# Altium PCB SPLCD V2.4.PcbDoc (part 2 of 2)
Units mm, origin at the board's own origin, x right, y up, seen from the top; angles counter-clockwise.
Board outline 130.07 x 120.05 mm, 4 copper layers (TopLayer, GND, PWR, BottomLayer); 151 components, 101 nets, 494 pads, 228 vias.
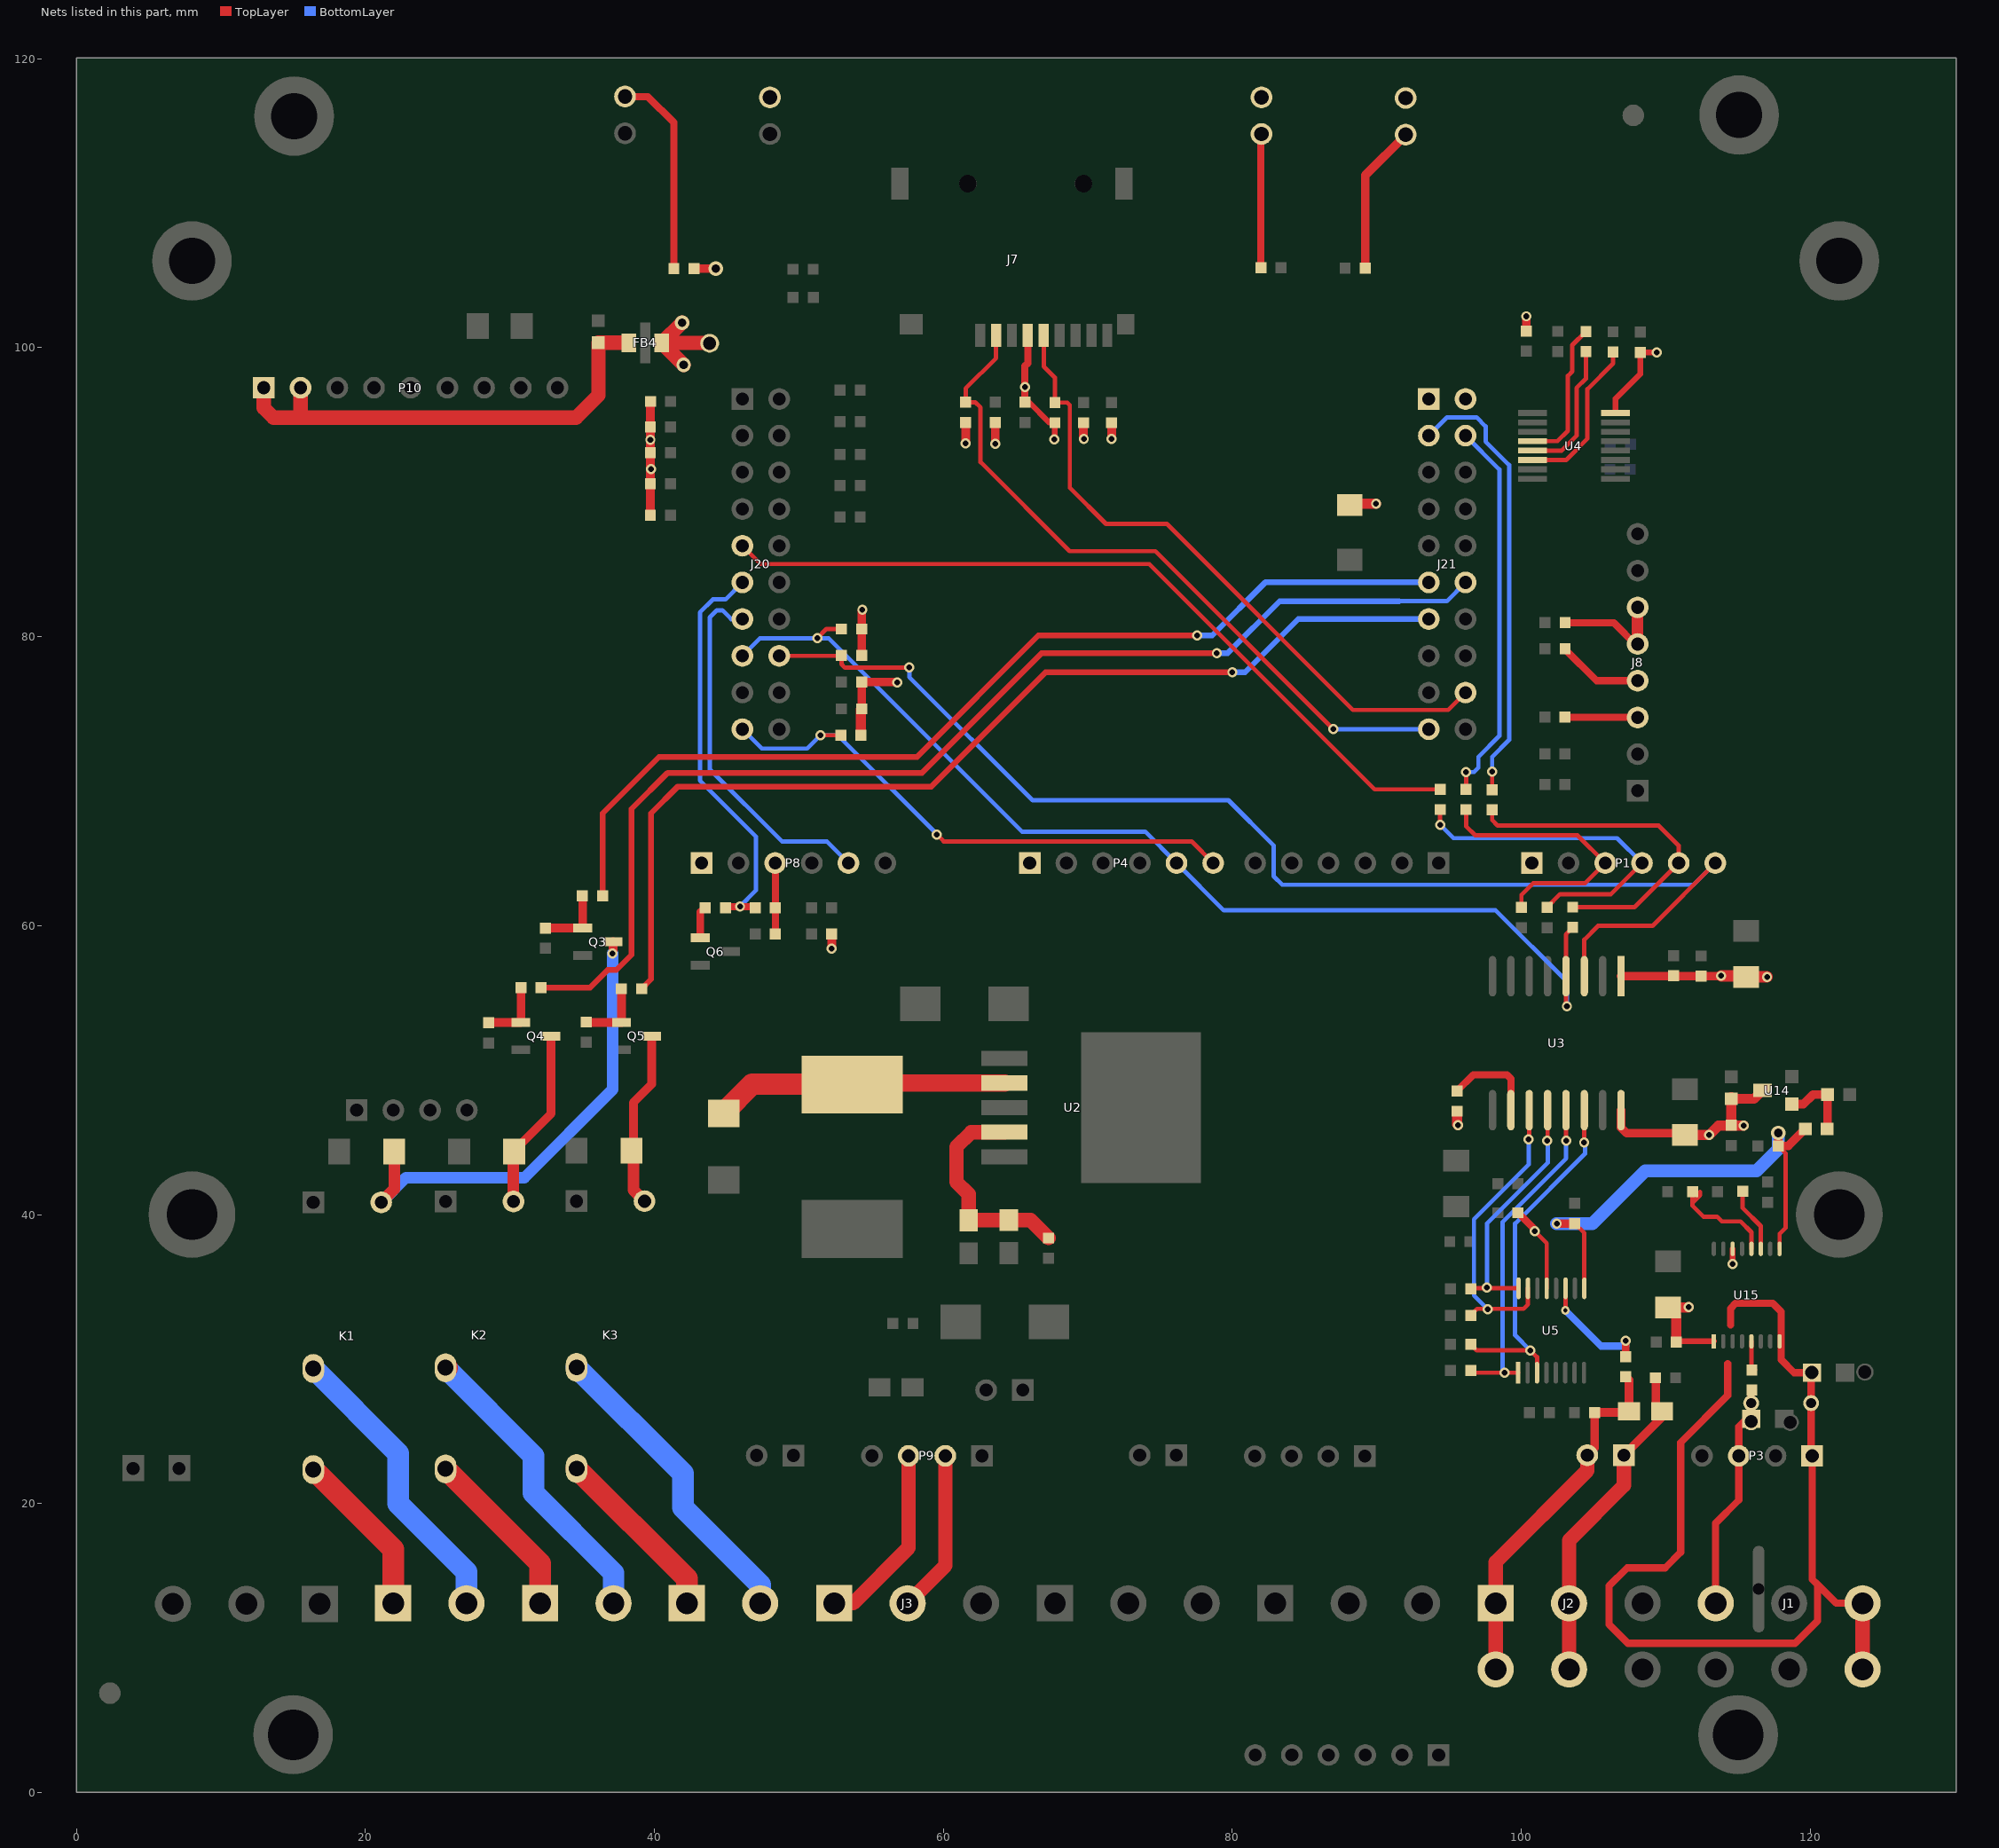
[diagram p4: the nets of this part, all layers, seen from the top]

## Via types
v1: diameter 0.7, hole 0.4, TopLayer to BottomLayer, 185 vias
v2: diameter 1, hole 0.6, TopLayer to BottomLayer, 40 vias
v3: diameter 0.6, hole 0.3, TopLayer to BottomLayer, 3 vias

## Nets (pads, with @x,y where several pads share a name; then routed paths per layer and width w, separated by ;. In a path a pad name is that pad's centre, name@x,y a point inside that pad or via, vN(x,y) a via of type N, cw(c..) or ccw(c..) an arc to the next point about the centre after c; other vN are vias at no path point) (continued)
NetC34_1: C34.1 FB6.1 U14.1 | length 5.1
  TopLayer w0.6: U14.1@118.725,47.642 119.517,47.642 120.174,48.299 C34.1@121.188,48.299 121.188,45.952 FB6.1@121.162,45.926
NetC39_1: C39.1 U4.5 | length 9.6
  TopLayer w0.3: U4.5@100.769,92.875 102.794,92.875 103.819,93.9 103.819,97.2 104.469,97.85 C39.1@104.469,99.725 C39.1@104.494,99.7
NetC39_2: C39.2 U4.4 | length 10.1
  TopLayer w0.3: U4.4@100.769,93.525 102.494,93.525 103.219,94.25 103.219,98.05 103.519,98.35 103.519,100.172 C39.2@104.469,101.122
NetC40_1: C40.1 U4.6 | length 11.1
  TopLayer w0.3: U4.6@100.769,92.225 103.094,92.225 104.569,93.7 104.569,97.125 106.344,98.9 C40.1@106.344,99.7
NetCF_1: CF.1 RF1.2 RF2.2 U2.4 | length 15.2
  TopLayer w1: U2.4@64.225,45.7 61.925,45.7 60.9,44.675 60.9,42.25 61.742,41.408 RF2.2@61.742,39.596 61.762,39.615 CF.1@64.533,39.615 66.032,39.615 RF1.2@67.275,38.372
NetD2_2: D2.2 L4.1 U2.2 | length 19.2
  TopLayer w1.2: L4.1@54.819,49.1 U2.2@64.225,49.1
  TopLayer w1.5: D2.2@44.8,47.05 46.775,49.025 L4.1@53.775,49.025
NetD7_1: D7.1 K1.3 Q3.3 | length 33.3
  TopLayer w0.6: v1@37.144,58.075 Q3.3@37.144,58.875
  TopLayer w0.8: K1.3@21.094,40.85 22,41.755 D7.1@22,44.347
  BottomLayer w0.8: K1.3@21.094,40.85 22.795,42.55 31,42.55 37.1,48.65 v1(37.1,58.075)
NetD8_1: D8.1 K2.3 Q4.3 | length 12.3
  TopLayer w0.6: D8.1@30.29,44.372 30.29,44.421 32.85,46.981 Q4.3@32.85,52.35
  TopLayer w0.8: K2.3@30.244,40.9 D8.1@30.244,44.125
NetD10_1: D10.1 K3.3 Q5.3 | length 12.2
  TopLayer w0.6: D10.1@38.55,44.557 38.55,47.756 39.819,49.025 Q5.3@39.819,52.35
  TopLayer w0.8: D10.1@38.415,44.422 38.55,44.288 38.55,41.694 K3.3@39.32,40.925
NetF3_1: 
NetFB4_1: FB4.1 P10.1 P10.2 VR2.2 | length 33.1
  TopLayer w1: P10.1@12.975,97.225 12.975,95.825 13.65,95.15 16.575,95.15 34.575,95.15 36.124,96.699 VR2.2@36.124,100.338 FB4.1@38.2,100.338 ; 15.515,95.275 P10.2@15.515,97.225
NetJ8_3: J8.3 R32.1 | length 5
  TopLayer w0.5: R32.1@103.066,74.425 J8.3@108.041,74.425 ; J8.3@108.021,74.425 J8.3@108.041,74.405
NetJ8_4: J8.4 R33.1 | length 5.9
  TopLayer w0.5: R33.1@103.025,79.125 105.2,76.95 108.036,76.95 J8.4@108.041,76.945
NetJ8_5: J8.5 J8.6 R34.1 | length 8.2
  TopLayer w0.5: R34.1@103.025,80.95 106.406,80.95 J8.5@107.956,79.4
  TopLayer w0.8: J8.5@108.041,79.485 J8.6@108.041,82.025
  TopLayer w1: J8.5@107.956,79.4 J8.5@108.041,79.485
NetJ9_1: J9.1 K1.7 | length 11.5
  TopLayer w1.5: K1.7@16.394,22.35 21.919,16.825 J9.1@21.919,13.1
NetJ9_2: J9.2 K1.1 | length 20.6
  BottomLayer w1.5: K1.1@16.394,29.35 22.269,23.475 22.269,20 26.999,15.27 J9.2@26.999,13.1
NetJ10_1: J10.1 K2.7 | length 12
  TopLayer w1.5: K2.7@25.544,22.4 32.094,15.85 J10.1@32.094,13.1
NetJ10_2: J10.2 K2.1 | length 21.2
  TopLayer w1.5: K2.1@25.544,29.4 K2.1@25.644,29.4
  BottomLayer w1.5: K2.1@25.544,29.4 31.644,23.3 31.644,20.725 37.174,15.195 J10.2@37.174,13.1
NetJ11_1: J11.1 K3.7 | length 12.5
  TopLayer w1.5: K3.7@34.619,22.425 42.244,14.8 J11.1@42.244,13.1
NetJ11_2: J11.2 K3.1 | length 21.6
  BottomLayer w1.5: K3.1@34.619,29.425 41.969,22.075 41.969,19.731 47.324,14.376 J11.2@47.324,13.1
NetLD1_1: LD1.1 R18.1 | length 14.2
  TopLayer w0.5: LD1.1@37.969,117.375 39.55,117.375 41.35,115.575 R18.1@41.35,105.475
NetLD2_2: LD2.2 R36.2 | length 9.4
  TopLayer w0.5: R36.2@81.969,105.45 81.969,114.735 LD2.2@82.019,114.785
NetLD3_2: LD3.2 R37.2 | length 10.4
  TopLayer w0.6: R37.2@89.197,105.5 89.197,111.937 LD3.2@91.995,114.735
NetP1_3: P1.3 R4.2 R28.1 | length 19.5
  TopLayer w0.3: R4.2@96.175,68.028 96.175,66.875 96.8,66.25 103.88,66.25 P1.3@105.805,64.325 104.405,62.925 100.8,62.925 100,62.125 R28.1@100,61.175
NetP1_4: P1.4 R5.2 R27.1 | length 24
  TopLayer w0.3: v1(94.375,66.975) R5.2@94.375,68.028 ; R27.1@101.775,61.275 102.675,62.175 106.195,62.175 P1.4@108.345,64.325
  BottomLayer w0.3: v1(94.375,66.975) 95.3,66.05 106.62,66.05 P1.4@108.345,64.325
NetP1_5: P1.5 R7.2 R13.1 | length 24.2
  TopLayer w0.3: R7.2@97.975,68.003 97.975,67.3 98.35,66.925 109.5,66.925 110.885,65.54 P1.5@110.885,64.325 107.835,61.275 R13.1@103.55,61.275
NetQ3_1: Q3.1 R50.1 R51.1 | length 4.8
  TopLayer w0.6: R51.1@32.469,59.825 Q3.1@35.044,59.825 35.044,62.025 R50.1@35.02,62.05
NetQ4_1: Q4.1 R53.1 R54.1 | length 4.6
  TopLayer w0.6: R54.1@28.544,53.275 28.569,53.3 30.744,53.3 30.769,53.325 R53.1@30.769,55.7
NetQ5_1: Q5.1 R55.1 R58.1 | length 4.8
  TopLayer w0.6: R58.1@35.294,53.325 35.319,53.3 Q5.1@37.719,53.3 R55.1@37.719,55.625
NetQ6_1: Q6.1 R47.1 | length 2.3
  TopLayer w0.5: Q6.1@43.175,59.15 43.175,60.95 R47.1@43.525,61.3
NetR2_2: R2.2 U5.11 | length 7.8
  TopLayer w0.3: v3(103.045,33.375) 103.056,33.386 U5.11@103.056,34.896
  TopLayer w0.5: R2.2@107.22,30.172 v1(107.22,31.275)
  BottomLayer w0.5: v3(103.045,33.375) 105.52,30.9 107.22,30.9
NetR20_1: R20.1 U15.12 | length 7.9
  TopLayer w0.3: R20.1@111.844,41.575 111.844,40.822 ; 112.37,41.575 112.37,41.348 111.844,40.822 ; U15.12@115.919,37.625 115.919,38.775 115.169,39.525 113.869,39.525 113.544,39.85 112.594,39.85 111.844,40.6 111.844,40.822
NetR23_1: R23.1 U3.10 | length 6.5
  TopLayer w0.5: R23.1@95.545,48.55 96.67,49.675 98.995,49.675 99.275,49.395 U3.10@99.275,47.229
NetR24_2: R24.2 U15.5 | length 2.1
  TopLayer w0.3: U15.5@115.919,31.225 115.919,29.503 R24.2@116.175,29.247
NetR25_1: R25.1 U15.11 | length 4.5
  TopLayer w0.3: R25.1@115.319,41.6 115.319,40.45 116.569,39.2 U15.11@116.569,37.625
PH-INP: C37.1 J1.1 P3.3 pad.@115.9,25.675 pad.@115.9,26.95 R24.1 | length 16
  TopLayer w0.5: J1.1@113.444,13.1 113.444,18.644 115.045,20.245 P3.3@115.045,23.3 115.045,25.32 115.525,25.8 115.9,25.8 pad.@115.9,26.95 R24.1@115.9,27.85
PH-VCM: C36.1 J1.3 P3.1 pad.6 pad.@120.1,29.075 pad.@120.05,26.95 U15.8 | length 74.8
  TopLayer w0.5: 114.275,29.675 114.275,27.475 111.025,24.225 111.025,16.625 109.95,15.55 107.325,15.55 106.075,14.3 106.075,11.625 107.375,10.325 118.925,10.325 120.487,11.887 120.487,14.387 ; 114.475,32.35 114.475,33.5 114.825,33.85 117.4,33.85 117.975,33.275 117.975,29.95 118.867,29.058 120.05,29.058 pad.@120.05,26.95 P3.1@120.05,23.3 ; P3.1@120.125,23.175 120.125,14.75 120.487,14.387 ; J1.3@123.604,13.1 121.775,13.1 120.487,14.387
  TopLayer w1: pad.6@123.61,8.525 J1.3@123.61,13.1
REL1_CON: J21.11 R50.2 | length 69.5
  TopLayer w0.4: R50.2@36.417,62.05 36.417,67.767 40.325,71.675 58.175,71.675 66.575,80.075 v1(77.55,80.075)
  BottomLayer w0.4: v1(77.55,80.075) 78.6,80.075 82.275,83.75 J21.11@93.594,83.75
REL2_CON: J21.12 R53.2 | length 81.5
  TopLayer w0.4: R53.2@32.166,55.7 35.55,55.7 36.775,56.925 37.375,56.925 38.425,57.975 38.425,68.075 40.925,70.575 58.525,70.575 66.8,78.85 v1(78.925,78.85)
  BottomLayer w0.3: 91.525,82.45 94.835,82.45 J21.12@96.134,83.75
  BottomLayer w0.4: v1(78.925,78.85) 79.669,78.85 83.269,82.45 91.525,82.45
RS485+: J3.2 P9.2 | length 11.3
  TopLayer w1: J3.2@57.524,13.1 60.135,15.711 P9.2@60.135,23.3
RS485-: J3.1 P9.3 | length 13.1
  TopLayer w1: J3.1@52.444,13.1 53.75,13.1 57.595,16.945 P9.3@57.595,23.3
RS485IN_DE: J20.9 R5.1 | length 55.3
  TopLayer w0.3: J20.9@46.094,86.29 47.36,85.025 74.25,85.025 89.85,69.425 R5.1@94.375,69.425
RS485IN_RX: J21.3 R7.1 | length 31
  TopLayer w0.3: R7.1@97.975,69.4 v1(97.975,70.65)
  BottomLayer w0.3: J21.3@93.594,93.91 94.86,95.175 96.9,95.175 97.525,94.55 97.525,93.5 99.15,91.875 99.15,72.85 97.975,71.675 v1(97.975,70.65)
RS485IN_TX: J21.4 R4.1 | length 26.7
  TopLayer w0.3: R4.1@96.175,69.425 v1(96.175,70.625)
  BottomLayer w0.3: J21.4@96.134,93.91 98.475,91.57 98.475,73.125 97.025,71.675 97.025,70.925 96.725,70.625 v1(96.175,70.625)
RX485: J20.13 P8.5 | length 25.5
  BottomLayer w0.3: J20.13@46.094,81.21 45.315,81.21 44.7,81.825 44.325,81.825 43.825,81.325 43.825,70.825 48.825,65.825 51.935,65.825 P8.5@53.435,64.325
SCK1: J20.15 P4.5 R13.2 R40.2 U3.4 | length 76.5
  TopLayer w0.3: v1(51.269,79.9) 51.894,80.525 R40.2@52.947,80.525 ; v1(103.15,54.425) 103.085,54.491 U3.4@103.085,56.5 103.085,59.388 R13.2@103.45,59.753
  BottomLayer w0.3: J20.15@46.094,78.67 47.3,79.875 52.069,79.875 65.444,66.5 73.96,66.5 P4.5@76.135,64.325 79.41,61.05 98.225,61.05 103.15,56.125 v1(103.15,54.425)
SCK2: J7.5 J21.18 R15.1 | length 46
  TopLayer w0.3: J7.5@66.944,100.85 66.944,98.7 67.719,97.925 R15.1@67.719,96.2 68.569,96.2 68.75,96.019 68.75,90.3 71.25,87.8 75.47,87.8 88.344,74.925 94.93,74.925 J21.18@96.134,76.13
SPI_CS: R6.2 U3.14 U5.3 | length 25.2
  TopLayer w0.3: R6.2@96.492,31.025 96.917,30.6 v1(100.62,30.6) 101.084,30.136 U5.3@101.084,29.054 ; v1@104.345,44.9 104.345,47.219 U3.14@104.355,47.229
  BottomLayer w0.3: v1(100.62,30.6) 99.57,31.65 99.57,39.375 104.4,44.206 v1@104.4,45
  other v1: 104.345,45
SPI_DIN: R10.2 U3.12 U5.16 | length 17.4
  TopLayer w0.3: R10.2@96.492,34.85 96.538,34.896 U5.16@99.806,34.896 ; v1@101.815,45.02 U3.12@101.815,47.229
  BottomLayer w0.3: v1(97.62,34.95) 97.62,39.375 101.825,43.581 v1@101.825,45.1
  other v1: 101.795,45.1
SPI_DOUT: R12.2 U3.11 U5.15 | length 21.2
  TopLayer w0.3: R12.2@96.492,33.025 96.942,33.475 100.145,33.475 100.456,33.786 U5.15@100.456,34.896 ; v1@100.545,45.15 U3.11@100.545,47.229
  BottomLayer w0.3: v1(97.67,33.45) 96.72,34.4 96.72,39.675 100.5,43.456 v1@100.5,45.2
  other v1: 100.495,45.2
SPI_SCLK: R9.2 U3.13 U5.1 | length 23.5
  TopLayer w0.3: R9.2@96.492,29.2 96.638,29.054 v1(98.845,29.054) U5.1@99.784,29.054 ; U3.13@103.085,47.229 103.095,47.219 v1@103.095,45
  BottomLayer w0.3: v1(98.845,29.054) 98.695,29.204 98.695,39.475 103.1,43.881 v1@103.1,45.1
  other v1: 103.095,45.1
SSEL1: J20.16 P1.6 R35.2 U3.3 | length 87.8
  TopLayer w0.3: J20.16@48.634,78.67 52.917,78.67 R35.2@52.947,78.7 52.947,78.097 53.194,77.85 57.619,77.85 v1(57.644,77.875) ; U3.3@104.355,56.5 104.355,59.03 105.3,59.975 109.075,59.975 P1.6@113.425,64.325
  BottomLayer w0.3: v1(57.644,77.875) 57.644,77.206 66.175,68.675 79.725,68.675 82.85,65.55 82.85,63.425 83.45,62.825 111.925,62.825 P1.6@113.425,64.325
SSEL1_A: J20.19 P4.6 R30.2 | length 38.6
  TopLayer w0.3: v1(51.5,73.175) R30.2@52.9,73.175 ; v1(59.55,66.3) 60.025,65.825 77.175,65.825 P4.6@78.675,64.325
  BottomLayer w0.3: J20.19@46.094,73.59 47.434,72.25 50.575,72.25 v1(51.5,73.175) 52.7,73.175 59.562,66.313 v1@59.6,66.275
SSEL2: J7.2 J21.19 R26.1 | length 49.1
  TopLayer w0.3: J7.2@63.644,100.85 63.644,99.275 61.544,97.175 R26.1@61.544,96.225 62.194,96.225 62.569,95.85 62.569,92.081 68.735,85.915 74.669,85.915 v1(86.994,73.59)
  BottomLayer w0.3: v1(86.994,73.59) J21.19@93.594,73.59
TIMER_CON: J21.13 R55.2 | length 71.8
  TopLayer w0.4: R55.2@39.116,55.625 39.775,56.284 39.775,67.775 41.625,69.625 59.175,69.625 67.075,77.525 v1(80,77.525)
  BottomLayer w0.4: v1(80,77.525) 80.869,77.525 84.554,81.21 J21.13@93.594,81.21
TP-IN+: J2.1 P2.2 pad.1@98.225,8.525 R2.1 R3.1 R21.2 | length 24.9
  TopLayer w0.6: P2.2@104.56,23.35 105.07,23.86 R3.1@105.07,26.3 R21.2@106.848,26.3 ; R2.1@107.22,28.775 107.454,28.541 R21.2@107.454,26.392
  TopLayer w1: pad.1@98.219,8.525 98.219,15.944 104.56,22.285 P2.2@104.56,23.35
TP-IN-: J2.2 P2.1 pad.2@103.305,8.525 R21.1 R22.1 | length 22.6
  TopLayer w0.6: P2.1@107.1,23.35 109.74,25.99 R21.1@109.74,26.392 109.3,26.832 109.3,28.25
  TopLayer w1: pad.2@103.299,8.525 103.299,17.449 107.1,21.25 P2.1@107.1,23.35
TX485: J20.11 R46.2 R47.2 | length 28.3
  TopLayer w0.3: R46.2@46.953,61.325 R46.2@46.978,61.3
  TopLayer w0.5: R47.2@44.922,61.3 R46.2@46.978,61.3
  BottomLayer w0.3: v1(45.925,61.325) 47.025,62.425 47.025,66.175 43.15,70.05 43.15,81.675 44.05,82.575 44.92,82.575 J20.11@46.094,83.75
TX485_C: P8.3 R46.1 R48.1 | length 4.8
  TopLayer w0.5: P8.3@48.355,64.325 48.375,64.305 R48.1@48.375,59.5
V330_D: C1.1 C4.2 C9.2 C27.2 C28.2 CA1.1 D6.2 FB4.2 J7.4 J21.1 J21.2 LD2.1 LD3.1 P1.1 P4.1 P8.1 PQ1.1 R1.2 R14.2 R15.2 R17.2 R18.2 R26.2 R30.1 R35.1 R39.1 R40.1 R43.1 R44.1 R59.2 R60.2 R61.2 R62.2 R63.2 TP5.1 U3.1 U4.16 | length 60
  TopLayer w0.4: C4.2@65.644,96.222 65.922,96.222 67.341,94.803 R15.2@67.719,94.803 v1@67.719,93.7 ; U4.16@106.51,95.475 106.51,96.46 108.225,98.175 C27.2@108.225,99.673 v1@109.372,99.673
  TopLayer w0.5: C4.2@65.644,96.222 v1(65.644,97.275) 65.644,98.725 65.844,98.925 J7.4@65.844,100.85
  TopLayer w0.6: R63.2@39.722,88.4 R62.2@39.722,90.575 R61.2@39.722,92.725 v1(39.722,93.625) R60.2@39.722,94.5 R59.2@39.722,96.175 ; R18.2@42.747,105.475 v2(44.25,105.475) ; v1(52.275,58.4) R39.1@52.275,59.425 ; R44.1@54.344,75 R43.1@54.344,76.85 v1@56.775,76.85 ; R35.1@54.344,78.7 R40.1@54.344,80.525 v1@54.344,81.8 ; v1(61.544,93.375) R26.2@61.544,94.828 ; v1(63.594,93.35) R17.2@63.594,94.828 ; v1@69.694,93.7 R14.2@69.694,94.803 ; v1(71.644,93.675) R1.2@71.644,94.803 ; C28.2@100.344,101.147 v1(100.344,102.17) ; U3.1@106.895,56.5 106.898,56.503 C9.2@112.445,56.503 114.625,56.503
  TopLayer w0.7: R30.1@54.297,73.175 R44.1@54.297,74.953 ; D6.2@88.1,89.202 v1(89.948,89.202)
  TopLayer w0.8: v1(113.825,56.52) 115.477,56.52 CA1.1@115.55,56.447 v1(116.998,56.447)
  TopLayer w1: v2(41.911,101.725) FB4.2@40.511,100.325 ; v2(42.025,98.811) FB4.2@40.511,100.325 ; TP5.1@43.475,100.325 FB4.2@40.511,100.325
  other v1: 56.8,76.825 54.394,81.85 39.769,91.6 67.669,93.65 69.719,93.675 109.375,99.675
VDD_ISO: C3.1 C8.1 C24.1 C25.1 CA2.1 FB1.1 R23.2 U3.16 U5.13 U14.3 U15.1 U15.14 | length 29.1
  TopLayer w0.3: v1(100.92,38.85) 101.756,38.014 U5.13@101.756,34.896
  TopLayer w0.4: C25.1@110.875,31.225 U15.1@113.319,31.225 ; v1@114.619,36.57 U15.14@114.619,37.625
  TopLayer w0.5: FB1.1@99.77,40.125 100.92,38.975 v1(100.92,38.85)
  TopLayer w0.6: U3.16@106.895,47.229 106.895,46.025 107.291,45.629 CA2.1@111.068,45.629 ; CA2.1@111.193,45.629 CA2.1@111.32,45.502
  TopLayer w0.7: R23.2@95.545,47.153 95.545,46.256 v1(95.625,46.175) ; C25.1@110.725,31.175 110.725,32.997 C24.1@110.145,33.577 111.546,33.577 v1(111.569,33.6) ; CA2.1@111.32,45.502 v1(112.995,45.502) 113.643,46.15 v1(115.375,46.15) ; C8.1@114.52,46.175 C3.1@114.52,48.133 ; C3.1@114.526,48.013 116.099,48.013 U14.3@116.693,48.607
  other v1: 114.625,36.575
VREF: C33.1 C35.1 FB6.2 U5.9 U15.9 | length 35.3
  TopLayer w0.3: C35.1@103.695,39.375 104.356,38.714 U5.9@104.356,34.896 ; C33.1@117.775,44.75 118.275,44.25 118.275,39.075 117.869,38.669 U15.9@117.869,37.625
  TopLayer w0.6: v1(102.445,39.375) C35.1@103.695,39.375 ; v2(117.775,45.65) C33.1@117.775,44.75 118.462,44.75 FB6.2@119.638,45.926
  BottomLayer w0.9: v1(102.445,39.375) 104.925,39.375 108.575,43.025 116.275,43.025 117.775,44.525 v2(117.775,45.65)
pads on no net: J1.2 J7. J7.1 J7.8 J13.1 J13.2 J13.3 J13.4 J13.5 J13.6 P3.2 P4.3 P6.2 P7.1 P7.2 P8.6 P9.4 P10.5 U3.7 U4.7 U4.8 U4.9 U4.10 U5.2 U5.4 U15.2 U15.3 U15.7

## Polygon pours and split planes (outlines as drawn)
EARTH on BottomLayer "BottomLayer-No Net" (hatched 90Degree grid 0.3 track 0.3, remove dead copper, pour order 12): 95.7,8.975 95.7,0.25 95.775,0.175 11.875,0.175 11.875,8.975 11.975,9.075
+12V on BottomLayer "BottomLayer-No Net" (hatched 90Degree grid 0.3 track 0.3, remove dead copper, pour order 22): 29.475,105.425 29.475,89.6 34.75,89.6 34.75,103.45 32.775,105.425
+12V on BottomLayer "BottomLayer-No Net" (hatched 90Degree grid 0.3 track 0.3, remove dead copper, pour order 17): 110.6,108.55 117.575,108.55 117.6,108.525 118.075,108.525 118.075,98.9 117.975,98.8 110.675,98.8 110.6,98.725
EARTH on BottomLayer "BottomLayer-No Net" (hatched 90Degree grid 0.3 track 0.3, remove dead copper, pour order 19): 95.375,5.8 111.55,5.8 111.6,5.85 111.6,-0.05 111.7,-0.15 95.575,-0.15 95.375,0.05
GND_ISO on BottomLayer "BottomLayer-No Net" (hatched 90Degree grid 0.3 track 0.3, remove dead copper, pour order 23): 93.325,25.35 110.375,25.35 112.45,27.425 112.45,35.575 112.55,35.675 129.5,35.675 129.6,35.775 129.6,51.875 93.4,51.875 93.325,51.95
GND on BottomLayer "BottomLayer-No Net" (hatched 90Degree grid 0.3 track 0.3, remove dead copper, pour order 25): 44.975,103.375 44.975,58.05 44.975,57.575 93.35,57.575 97.4,53.525 118.325,53.525 118.425,53.425 118.425,95 110.025,103.4
no net on TopSolder "BottomLayer-No Net" (solid): 113.338,11.125 114.325,11.125 115.412,12.213 115.4,12.225 115.4,17.375 116.275,18.25 116.275,19.175 116.275,24.1 116.925,24.75 116.925,25.9 116.925,28.45 116.95,28.475 116.6,28.825 116.6,29.975 116.6,32.225 116.575,32.25 116.275,32.55 115.885,32.55 115.525,32.55 115.25,32.275 115.275,32.25 115.275,30.125 115.05,29.9 115.05,28.5 115.05,26.725 114.15,25.825 112.5,24.175 112.5,15.475 111.275,14.25 111.275,14.225 111.275,12.2 112.3,11.175 112.3,11.125
no net on BottomSolder "BottomLayer-No Net" (solid): 113.338,11.125 114.325,11.125 115.412,12.213 115.4,12.225 115.4,14.675 115.4,17.375 116.275,18.25 116.275,19.175 116.275,24.1 117,24.825 117,26.325 117,29.65 116.6,30.05 116.6,32.225 116.275,32.55 115.885,32.55 115.525,32.55 115.275,32.3 115.275,30.15 115.025,29.9 115.025,26.7 112.85,24.525 112.475,24.15 112.475,19.175 112.475,15.5 112.5,15.475 111.275,14.25 111.275,14.225 111.275,12.2 112.35,11.125
NetFB4_1 on TopLayer "BottomLayer-No Net" (hatched 90Degree grid 0.3 track 0.3, remove dead copper, pour order 18): 16.625,99.2 16.625,95.95 16.6,95.925 34.175,95.925 35.15,96.9 35.75,97.5 36.275,97.5 37.4,97.5 37.45,97.55 37.45,94.375 36.025,92.95 12.875,92.95 11.25,94.575 11,94.825 11,99.2
GND_ISO on TopLayer "BottomLayer-No Net" (hatched 90Degree grid 0.3 track 0.3, remove dead copper, pour order 20): 93.4,25.275 110.225,25.275 111.575,26.625 112.45,27.5 112.45,35.525 129.925,35.525 129.925,51.7 129.85,51.775 93.5,51.775 93.4,51.875
GND on TopLayer "BottomLayer-No Net" (hatched 90Degree grid 0.3 track 0.3, remove dead copper, pour order 21): 44.975,103.5 44.975,57.675 93.15,57.675 96.425,54.4 97.475,53.35 118.5,53.35 118.5,95.125 110.125,103.5
24VGND_IN on GND (split plane): 30.198,46.916 28.634,45.352 14.869,45.352 14.791,45.344 14.716,45.321 14.646,45.284 14.585,45.234 14.535,45.173 14.498,45.104 14.475,45.028 14.468,44.95 14.468,33.8 14.475,33.722 14.498,33.646 14.535,33.577 14.585,33.516 14.646,33.466 14.716,33.429 14.791,33.406 14.869,33.398 41.644,33.398 41.723,33.406 41.798,33.429 41.868,33.466 41.929,33.516 41.979,33.577 42.016,33.646 42.018,33.654 42.041,33.696 42.064,33.772 42.071,33.85 42.071,56.273 92.323,56.273 92.323,52.225 92.323,46.825 92.323,20.7 92.331,20.622 92.354,20.546 92.391,20.477 92.441,20.416 95.318,17.539 95.318,0.51 0.51,0.51 0.51,67.573 30.198,67.573
GND_ISO on GND (split plane): 129.565,0.51 96.121,0.51 96.121,17.706 96.114,17.784 96.091,17.859 96.054,17.929 96.004,17.99 93.127,20.866 93.127,51.823 129.565,51.823
GND on GND (split plane): 129.565,52.627 93.127,52.627 93.127,56.675 93.119,56.753 93.096,56.829 93.059,56.898 93.009,56.959 92.948,57.009 92.879,57.046 92.803,57.069 92.725,57.077 41.669,57.077 41.591,57.069 41.516,57.046 41.446,57.009 41.385,56.959 41.335,56.898 41.298,56.829 41.275,56.753 41.268,56.675 41.268,34.202 15.271,34.202 15.271,44.548 28.8,44.548 28.878,44.556 28.954,44.579 29.023,44.616 29.084,44.666 30.884,46.466 30.934,46.527 30.971,46.596 30.994,46.672 31.002,46.75 31.002,67.84 31.019,67.897 31.027,67.975 31.019,68.053 31.002,68.11 31.002,68.484 38.459,75.941 38.509,76.002 38.546,76.071 38.569,76.147 38.577,76.225 38.577,108.575 38.569,108.653 38.552,108.711 38.546,108.729 38.509,108.798 38.459,108.859 34.959,112.359 34.898,112.409 34.829,112.446 34.753,112.469 34.675,112.477 34.597,112.469 34.521,112.446 34.452,112.409 34.391,112.359 34.341,112.298 34.304,112.229 34.281,112.153 34.273,112.075 34.281,111.997 34.304,111.921 34.341,111.852 34.391,111.791 37.773,108.409 37.773,76.391 30.316,68.934 30.266,68.873 30.229,68.804 30.206,68.728 30.198,68.65 30.198,68.377 0.51,68.377 0.51,119.54 129.565,119.54
V330_D on PWR (split plane): 109.998,98.4 110.006,98.322 110.029,98.246 110.066,98.177 110.116,98.116 110.177,98.066 110.246,98.029 110.322,98.006 110.4,97.998 114.298,97.998 114.298,73.702 99.9,73.702 99.822,73.694 99.764,73.677 99.746,73.672 99.677,73.634 99.616,73.584 98.891,72.859 98.841,72.799 98.804,72.729 98.781,72.654 98.773,72.575 98.773,66.875 98.781,66.797 98.804,66.721 98.841,66.652 98.891,66.591 98.952,66.541 99.021,66.504 99.097,66.481 99.175,66.473 129.565,66.473 129.565,52.652 93.152,52.652 93.152,56.675 93.144,56.753 93.121,56.829 93.084,56.898 93.034,56.959 92.973,57.009 92.904,57.046 92.828,57.069 92.75,57.077 41.544,57.077 41.466,57.069 41.391,57.046 41.321,57.009 41.26,56.959 41.21,56.898 41.173,56.829 41.15,56.753 41.143,56.675 41.143,34.252 15.246,34.252 15.246,44.548 28.9,44.548 28.978,44.556 29.054,44.579 29.123,44.616 29.184,44.666 30.909,46.391 30.959,46.452 30.996,46.521 31.019,46.597 31.027,46.675 31.027,68.409 38.509,75.891 38.559,75.952 38.596,76.021 38.619,76.097 38.627,76.175 38.627,108.5 38.619,108.578 38.596,108.654 38.559,108.723 38.509,108.784 34.977,112.316 34.977,119.54 109.998,119.54
+12V on PWR (split plane): 129.565,67.277 99.577,67.277 99.577,72.409 100.066,72.898 114.7,72.898 114.778,72.906 114.854,72.929 114.923,72.966 114.984,73.016 115.034,73.077 115.071,73.146 115.094,73.222 115.102,73.3 115.102,98.4 115.094,98.478 115.071,98.554 115.034,98.623 114.984,98.684 114.923,98.734 114.854,98.771 114.778,98.794 114.7,98.802 110.802,98.802 110.802,119.54 129.565,119.54
VDD_ISO on PWR (split plane): 129.565,0.51 96.121,0.51 96.121,17.806 96.114,17.884 96.091,17.959 96.054,18.029 96.004,18.09 93.127,20.966 93.127,47.215 93.144,47.272 93.152,47.35 93.152,51.6 93.152,51.848 129.565,51.848
+12V on PWR (split plane): 34.173,112.15 34.181,112.072 34.204,111.996 34.241,111.927 34.291,111.866 37.823,108.334 37.823,76.341 30.341,68.859 30.291,68.798 30.254,68.729 30.231,68.653 30.223,68.575 30.223,68.277 0.51,68.277 0.51,119.54 34.173,119.54
+24V_IN on PWR (split plane): 30.223,46.841 28.734,45.352 14.844,45.352 14.766,45.344 14.691,45.321 14.621,45.284 14.56,45.234 14.51,45.173 14.473,45.104 14.45,45.028 14.443,44.95 14.443,33.85 14.45,33.772 14.473,33.696 14.51,33.627 14.56,33.566 14.621,33.516 14.691,33.479 14.766,33.456 14.844,33.448 41.354,33.448 41.391,33.429 41.466,33.406 41.544,33.398 41.623,33.406 41.698,33.429 41.768,33.466 41.829,33.516 41.879,33.577 41.916,33.646 41.939,33.722 41.946,33.8 41.946,56.273 92.348,56.273 92.348,52.385 92.331,52.328 92.323,52.25 92.323,20.8 92.331,20.722 92.354,20.646 92.391,20.577 92.441,20.516 95.318,17.639 95.318,0.51 0.51,0.51 0.51,67.473 30.223,67.473

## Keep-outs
KeepOutLayer:
  lines w0.5: -0.01,103.25 cw(c2.989,103.171) 2.565,106.14 ; 0,7.639 ccw(c2.99,7.889) 2.275,4.975 ; 10.986,2.374 ccw(c13.92,2.998) 14.475,0.05 ; 12.15,116.75 cw(c15.132,117.081) 15.407,120.069 ; 12.2,112.575 cw(c8.578,112.259) 8.109,108.654 ccw(c8.132,105.69) 5.2,106.125 0.275,106.125 0,105.85 0,4.975 6.8,4.975 cw(c6.7,0.15) 11.525,0.05 118.525,0.05 ; 12.2,112.675 12.2,120.075 117.85,120.075 117.85,111.325 ; 52.147,119.997 56.094,116.05 73.269,116.05 77.247,120.028 ; 114.755,120.025 cw(c114.912,117.03) 117.9,117.3 ; 117.075,0.05 ccw(c115.989,2.846) 118.858,1.97 ; 117.25,120.07 cw(c116.5,118.925) 117.85,118.7 ; 117.91,111.396 ccw(c120.76,111.325) 120.825,108.475 cw(c121.408,104.961) 124.775,106.125 ; 118.5,0.05 cw(c123.462,0.063) 123.45,5.025 ; 123.462,5.025 130.125,5.025 130.125,106.125 124.775,106.125 ; 126.75,5.025 ccw(c127.362,7.962) 130.094,6.723 ; 127.29,106.111 cw(c127.201,103.113) 130.152,103.655 ; 130.1,67.025 128.975,68.15 126.25,68.15 125.4,69 125.4,89.8 126.25,90.65 128.95,90.65 130.162,91.863

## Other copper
GND (plane layer: these items are gaps in the copper):
  pour cut-out: 104.975,10 117.05,10 117.05,33.9 117.075,33.925 114.225,33.925 114.175,33.975 114.175,27.375 111.825,25.025 109.8,25.025 109.825,17.775 104.975,17.775
  lines w0.8: 0.025,67.975 30.625,67.975 ; 34.675,112.075 38.175,108.575 38.175,76.225 30.6,68.65 30.6,46.75 28.8,44.95 14.869,44.95 14.869,33.8 41.644,33.8 ; 41.669,33.85 41.669,56.675 92.725,56.675 92.725,46.825 ; 95.719,0.15 95.719,17.706 92.725,20.7 92.725,52.225 130.15,52.225
PWR (plane layer: these items are gaps in the copper):
  pour cut-out: 104.95,10.075 117.075,10.075 117.075,33.9 116.925,34.05 114.25,34.05 114.175,33.975 114.175,27.525 111.675,25.025 109.7,25.025 109.7,17.85 104.95,17.85
  lines w0.8: 0.05,67.875 30.625,67.875 ; 34.575,120.125 34.575,112.15 38.225,108.5 38.225,76.175 30.625,68.575 30.625,46.675 28.9,44.95 14.844,44.95 14.844,33.85 41.544,33.85 ; 41.544,33.8 41.544,56.675 92.75,56.675 92.75,51.6 92.75,47.35 ; 95.719,0.05 95.719,17.806 92.725,20.8 92.725,52.25 129.85,52.25 ; 110.4,120 110.4,98.4 114.7,98.4 114.7,73.3 99.9,73.3 99.175,72.575 99.175,66.875 129.975,66.875

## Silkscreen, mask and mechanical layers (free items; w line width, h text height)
TopOverlay:
  lines w0.2: 109.311,68.055 115.189,68.055 115.244,68.11 115.244,88.375 109.311,88.375 ; 115.219,69.925 113.219,69.925 113.219,70.875 115.244,70.875 ; 115.244,85.75 113.194,85.75 113.194,86.775 115.244,86.775 ; 91.625,26.225 91.625,30.125 73.15,30.125 73.15,26.225 91.625,26.225 ; 91.625,26.225 91.625,26.225
  lines w0.3: 5.475,99.15 5.475,45.225 40.675,45.225 40.675,99.175 5.5,99.175 ; 41.625,16.85 41.625,67.2 64.025,67.2 ; 64.025,58.375 64.025,67.225 93.175,67.225 ; 91.625,26.225 91.625,20.894 95.669,16.85 93.175,19.344 93.175,63.075 ; 26.52,116.85 27.27,116.85 27.27,111.875 27.295,111.85 28.22,111.85 28.22,116.725 28.27,116.775 29.095,116.775 27.77,118.1 26.52,116.85
  lines w0.4: 20.475,8.625 20.475,6.575 21.5,6.575 ; 26.65,6.575 27.95,6.575 27.95,8.775 ; 30.75,8.7 30.75,6.575 31.775,6.575 ; 36.925,6.575 38.225,6.575 38.225,8.675 ; 40.975,8.675 40.975,6.6 41.6,6.6 ; 47.825,6.6 48.45,6.6 48.45,8.65 ; 51.075,7.925 51.075,9 ; 58.725,7.9 58.725,9.025 ; 71.125,7.425 71.125,8.825 ; 78.7,7.65 78.7,8.725 ; 81.6,7.375 81.6,8.775 ; 89.175,7.6 89.175,8.775 ; 45.419,99.125 46.594,99.125 46.007,98.538 45.419,99.125 ; 92.969,99.125 94.144,99.125 93.557,98.538 92.969,99.125
  text "Sanpell_SP2100RS_V2.4 20.03" at 79.95,110.275 h1.5
  text "+ 3.3V -" at 13.675,93.925 h1
  text "- 12V +" at 26.6,93.925 h1
  text "GND" at 103.75,86.625 h1
  text "GND" at 103.775,84.175 h1
  text "TX" at 104.45,81.475 h1
  text "TX" at 104.475,79.05 h1
  text "DC-DC modue" at 17.725,77.55 h1
  text "RX" at 104.6,76.45 h1
  text "BY" at 104.625,73.975 h1
  text "VCC" at 103.925,71.375 h1
  text "VCC" at 103.925,68.775 h1
  text "LCD" at 112.425,66.4 h1
  text "KEY" at 83.2,61.15 h1
  text "485_module" at 53.4,57.375 h1
  text "AO_module" at 69.725,57.375 h1
  text "+ 24V -" at 20.5,50.45 h1
  text "485: V+ V- NC B A PE" at 73.775,28.65 h1
  text "AIN: V+ V- A1 COM A2" at 74.275,26.85 h1
  text "C32" at 120.95,26.625 h0.8
  text "NC" at 117.245,17.9 h1.5
  text "GUARD" at 105.075,17.825 h1.5
  text "INP" at 112.525,17.825 h1.5
  text "VCM" at 121.675,17.825 h1.5
  text "T+" at 96.745,17.725 h1.5
  text "T-" at 101.52,17.725 h1.5
  text "+ DC -" at 10.125,7.15 h1.5
  text "PE" at 4.7,7.075 h1.5
  text "B(485)A" at 50.869,6 h1.5
  text "+B(mA)-" at 70.22,6 h1.5
  text "PE" at 61.55,5.975 h1.5
  text "-A(mA)+" at 80.644,5.975 h1.5
  text "PE" at 66.55,5.925 h1.5
  text "REL1" at 22.045,5.8 h1.5
  text "REL2" at 32.144,5.8 h1.5
  text "WASH" at 41.869,5.8 h1.5
  text "NC" at 92.369,5.8 h1.5
TopSolder:
  lines w0.3: 114.3,11.125 113.338,11.125 114.325,11.125 ; 114.325,11.125 112.3,11.125 111.275,12.15 111.275,14.225 112.5,15.45 112.5,15.475 112.475,15.5 112.475,24.275 114.025,25.825 114.15,25.825 115.05,26.725 115.05,28.5 115.05,29.9 115.275,30.125 115.275,31.175 115.25,31.2 115.25,32.275 115.525,32.55 115.885,32.55 116.275,32.55 116.575,32.25 116.575,31.275 116.6,31.25 116.6,29.975 116.95,29.625 116.95,28.475 116.925,28.45 116.925,24.75 116.275,24.1 116.275,21.625 116.275,19.175 116.275,18.25 115.45,17.425 115.4,17.375 115.4,14.675 115.412,14.663 115.412,12.213 114.325,11.125
BottomSolder:
  lines w0.3: 111.275,12.2 112.35,11.125 113.338,11.125 114.325,11.125 115.4,12.2 115.4,17.375 116.275,18.25 116.275,19.175 116.275,24.1 116.95,24.775 116.95,28.475 116.95,29.7 116.6,30.05 116.6,32.225 116.275,32.55 115.885,32.55 115.525,32.55 115.275,32.3 115.275,30.15 115.025,29.9 115.025,26.7 114.15,25.825 112.475,24.15 112.475,21.65 112.5,21.625 112.5,15.475 111.275,14.25 111.275,12.2
Mechanical1:
  circle w0.254: c8,40 r5
  circle w0.254: c8,106 r6.6
  lines w0.2: 20.4,47.375 20.4,106.575 ; 49.635,20.275 49.635,66.965 ; 76.135,18.7 76.135,65.39 ; 107.075,20.98 107.075,64.3
  lines w0.25: -0.925,120.05 126.725,120.05 ; 34.85,60.175 138.875,60.175 ; 130.075,0.5 130.075,128.9
  lines w0.254: 39.425,19.175 137.125,19.175
  lines w0.3: -12.181,40.1 134.519,40.1 ; -6.8,4.975 132.125,4.975 ; -4.806,116.1 131.744,116.1 ; -2.806,0 132.044,0 ; -2.606,108.575 129.044,108.575 ; -2.281,4.05 132.794,4.05 ; -1.031,22.05 135.519,22.05 ; 0.011,1.5 0.011,115.55 ; 3.844,106.125 131.394,106.125 ; 7.919,37.375 7.919,124.575 ; 11.525,-1.225 11.525,6.875 ; 14.389,13.05 127.369,13.05 ; 15.019,0.5 15.019,118.225 ; 37.919,104.1 37.919,124.046 ; 45.269,96.498 100.344,96.498 ; 47.944,107.55 47.944,124.321 ; 64.969,-8.9 64.969,93.5 ; 64.969,93.225 64.969,126.65 ; 81.994,104.025 81.994,124.296 ; 91.719,-0.25 91.719,64.45 ; 91.994,104.3 91.994,124.171 ; 94.65,8.55 127.225,8.55 ; 97.675,65.125 136.025,65.125 ; 115.031,-1.225 115.031,118.5 ; 121.994,31.425 121.994,123.925

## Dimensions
49.625,21.105 to 57.6,20.93 on Mechanical13
93.4,16.25 to 130.125,5.025 on Mechanical13
93.425,21 to 107.05,21.055 on Mechanical13
76.135,22.301 to 84.11,22.126 on Mechanical13
84.11,22.301 to 92.925,20 on Mechanical13
64.436,26.801 to 92.911,23.651 on Mechanical13
66.925,67.2 to 67.175,19.225 on Mechanical1
108.075,64.7 to 130.071,63.925 on Mechanical1
137.07,19.175 to 138.05,60.175 on Mechanical1
134.519,40.1 to 136.025,65.125 on Mechanical1
11.975,110.825 to 0,111.75 on Mechanical1
130.129,104.774 to 118.1,111.325 on Mechanical1
132.88,40.085 to 134.305,106.11 on Mechanical1
64.966,123.254 to 7.925,123.2 on Mechanical1
0.011,115.55 to 64.969,126.65 on Mechanical1
0.794,4.075 to 0.745,22.05 on Mechanical1
-1.725,108.575 to -0.925,120.05 on Mechanical1
-4.581,4.05 to -3.781,116.1 on Mechanical1
-3.575,0 to -1.581,4.05 on Mechanical1
115.031,-1.225 to 130.075,0.5 on Mechanical1
96.123,89.775 to 46.123,87.35 on Mechanical1
0,-2.025 to 130.025,-3.25 on Mechanical1
-2.806,0 to -2.4,120.05 on Mechanical1
0,2.125 to 11.525,-1.225 on Mechanical1
0,0.375 to 15.019,0.5 on Mechanical1
130.719,106.1 to 130.569,116.1 on Mechanical1
122,123.175 to 64.966,123.225 on Mechanical1
64.969,126.65 to 81.994,125.125 on Mechanical1
47.944,126.625 to 64.969,125.1 on Mechanical1
47.944,124.55 to 37.919,123.675 on Mechanical1
81.994,124.296 to 91.994,124.1 on Mechanical1
56.437,63.376 to 51.112,103.351 on Mechanical1
-8.475,0 to -6.8,4.975 on Mechanical1
118.55,1.675 to 130.075,-1.675 on Mechanical1
107.075,21.23 to 115.05,21.055 on Mechanical13
127.225,8.55 to 127.199,13.044 on Mechanical1
35.625,95.875 to 0.625,95.35 on Mechanical1
6.625,97.225 to 7.25,47.225 on Mechanical1
40.701,96.989 to 33.276,98.564 on Mechanical1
